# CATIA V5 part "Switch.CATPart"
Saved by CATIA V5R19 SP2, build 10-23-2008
Part number: Switch.1
Revision: ANY
Definition: UNKNOWN
Nomenclature: Switch
Source: Unknown
Bounding box of the stored display mesh (mm): x -15 to 15, y 1 to 6.147, z -6 to 6
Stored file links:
  Z:\fausse table rondelle-20220905T211342Z-001\fausse table rondelle\Switch.CATPart
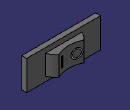
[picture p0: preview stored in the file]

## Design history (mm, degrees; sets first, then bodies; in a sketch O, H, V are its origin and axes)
AxisSystem1: origin (0, 0, 0), X (1, 0, 0), Y (0, 1, 0), Z (0, 0, 1)
Body1 "Aufsatz-Linear austragen2" (main body)
  Solid1: solid without history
